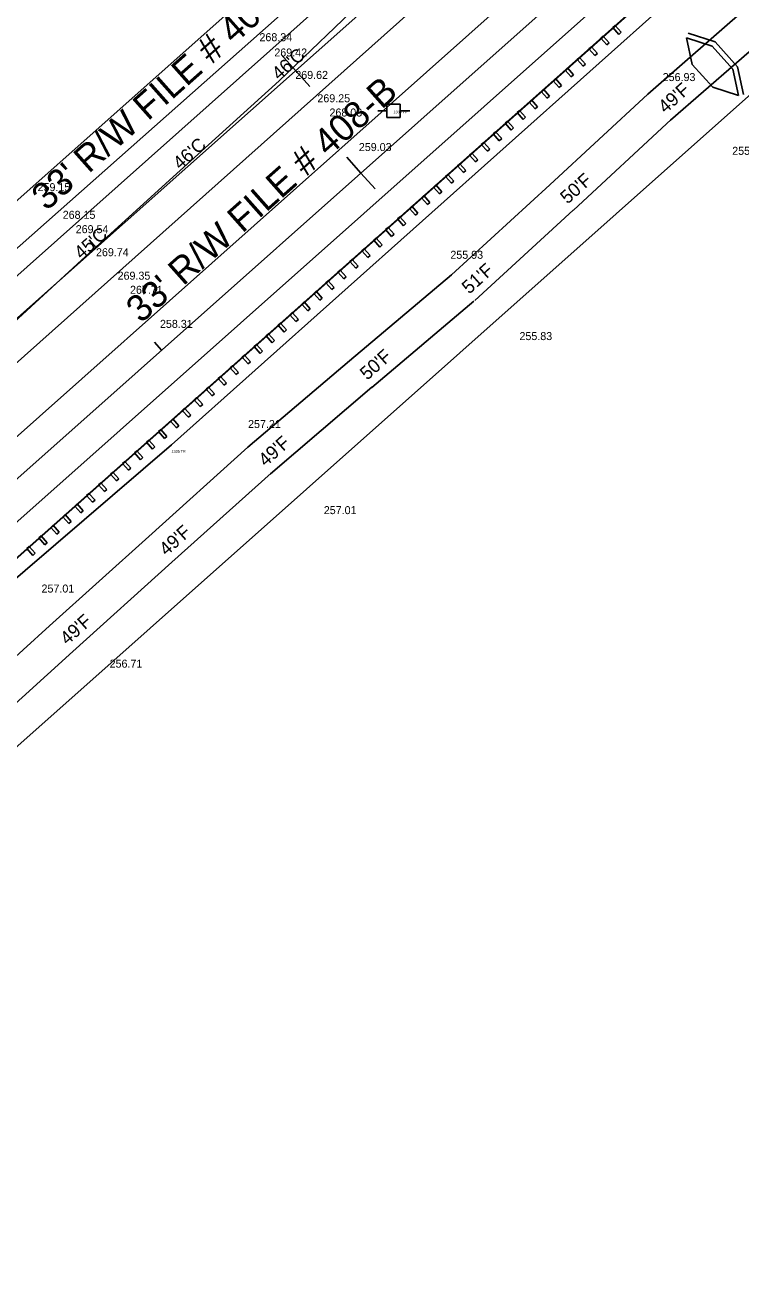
# Model space of a CAD drawing. Extents: x 49683 to 58852, y 49525 to 54803.
# Drawn here: x 53191 to 53459.4, y 50894.8 to 51364.8 of the extents above; entities that cross this region are included whole.
import ezdxf

# ---------------------------------------------------------------- set-up
doc = ezdxf.new("R2010")
doc.units = 0
for name, color, linetype in [('Level 1', 7, 'Continuous'), ('Level 11', 7, 'Continuous'), ('Level 13', 7, 'Continuous'), ('Level 18', 7, 'Continuous'), ('Level 19', 7, 'Continuous'), ('Level 20', 7, 'Continuous'), ('Level 25', 7, 'Continuous'), ('Level 27', 7, 'Continuous'), ('Level 3', 7, 'Continuous'), ('Level 32', 7, 'Continuous'), ('Level 33', 7, 'Continuous'), ('Level 34', 7, 'Continuous'), ('Level 48', 7, 'Continuous'), ('Level 59', 7, 'Continuous'), ('Level 61', 7, 'Continuous'), ('Level 9', 7, 'Continuous')]:
    doc.layers.add(name, color=color, linetype=linetype)

# ---------------------------------------------------------------- blocks, each defined once
blk = doc.blocks.new('PP')
at = {"layer": 'Level 9'}
for p, q in [((2.53, 2.45), (-2.47, 2.45)), ((-2.47, 2.45), (-2.47, -2.55)), ((2.53, -2.55), (2.53, 2.45)), ((-5.91, -0.11), (-2.44, -0.11)), ((-2.47, -2.55), (2.53, -2.55)), ((2.45, -0.11), (6.09, -0.11))]:
    blk.add_line(p, q, dxfattribs=at)

msp = doc.modelspace()

# ---------------------------------------------------------------- linework, layer by layer
at = {"layer": 'Level 1'}
for p, q in [((52544.81, 50683.3), (55534.58, 53340.86)), ((53292.35, 51347.78), (53287.03, 51353.76)), ((53297.66, 51341.8), (53292.35, 51347.78)), ((53217.61, 51281.34), (53214.95, 51284.33))]:
    msp.add_line(p, q, dxfattribs=at)
at = {"layer": 'Level 11'}
for p, q in [((53245.86, 51207.55), (53944.24, 51830.77)), ((53157.7, 51254.45), (53424.49, 51490.93)), ((52882.73, 50895.61), (53245.86, 51207.55))]:
    msp.add_line(p, q, dxfattribs=at)
at = {"layer": 'Level 13'}
for p, q in [((52637.37, 50809.73), (53363.85, 51455.49)), ((53407.7, 51406.16), (52566.74, 50658.64))]:
    msp.add_line(p, q, dxfattribs=at)
at = {"layer": 'Level 18'}
for p, q in [((53286.2, 51343.93), (53322.27, 51378.61)), ((53424.42, 51338.95), (53462.1, 51371.82)), ((53432.96, 51329.16), (53470.65, 51362.02)), ((53249.14, 51310.36), (53286.2, 51343.93)), ((53387.69, 51305.01), (53424.42, 51338.95)), ((53396.52, 51295.46), (53433.24, 51329.41)), ((53212.1, 51276.77), (53249.14, 51310.36)), ((53350.81, 51271.24), (53387.69, 51305.01)), ((53359.59, 51261.65), (53396.47, 51295.42)), ((53175.25, 51242.97), (53212.1, 51276.77)), ((53312.59, 51238.98), (53350.81, 51271.24)), ((53320.98, 51229.04), (53359.2, 51261.31)), ((53274.51, 51206.56), (53312.59, 51238.98)), ((53282.94, 51196.66), (53321.02, 51229.08)), ((53237.33, 51173.13), (53274.51, 51206.56)), ((53246.02, 51163.46), (53283.2, 51196.89)), ((53200.16, 51139.69), (53237.33, 51173.13)), ((53208.85, 51130.02), (53246.02, 51163.46)), ((53163.11, 51106.1), (53200.16, 51139.69)), ((53171.84, 51096.47), (53208.89, 51130.05))]:
    msp.add_line(p, q, dxfattribs=at)
at = {"layer": 'Level 19'}
for p, q in [((52714.15, 50773.62), (54181.77, 52078.16)), ((53316.9, 51309.39), (53311.58, 51315.37)), ((53316.9, 51309.39), (53322.21, 51303.41)), ((53242.16, 51242.96), (53239.5, 51245.95))]:
    msp.add_line(p, q, dxfattribs=at)
at = {"layer": 'Level 20'}
for p, q in [((52706.17, 50782.58), (53452.43, 51445.92)), ((52722.12, 50764.65), (53468.37, 51427.98))]:
    msp.add_line(p, q, dxfattribs=at)
at = {"layer": 'Level 27'}
for p, q in [((52957.81, 50960.77), (53475.02, 51420.51)), ((52957.97, 50960.58), (53475.18, 51420.32)), ((53411.35, 51363.91), (53412.23, 51364.7)), ((53413.61, 51361.37), (53411.35, 51363.91)), ((53412.23, 51364.7), (53414.49, 51362.16)), ((53406.87, 51359.93), (53407.75, 51360.71)), ((53409.13, 51357.39), (53406.87, 51359.93)), ((53407.75, 51360.71), (53410.01, 51358.17)), ((53414.49, 51362.16), (53413.61, 51361.37)), ((53402.38, 51355.94), (53403.27, 51356.73)), ((53404.64, 51353.4), (53402.38, 51355.94)), ((53403.27, 51356.73), (53405.52, 51354.19)), ((53405.52, 51354.19), (53404.64, 51353.4)), ((53410.01, 51358.17), (53409.13, 51357.39)), ((53397.9, 51351.96), (53398.78, 51352.74)), ((53400.16, 51349.41), (53397.9, 51351.96)), ((53398.78, 51352.74), (53401.04, 51350.2)), ((53401.04, 51350.2), (53400.16, 51349.41)), ((53388.93, 51343.98), (53389.81, 51344.77)), ((53389.81, 51344.77), (53392.07, 51342.23)), ((53393.41, 51347.97), (53394.3, 51348.76)), ((53395.67, 51345.43), (53393.41, 51347.97)), ((53394.3, 51348.76), (53396.56, 51346.21)), ((53396.56, 51346.21), (53395.67, 51345.43)), ((53384.44, 51340), (53385.33, 51340.78)), ((53385.33, 51340.78), (53387.59, 51338.24)), ((53391.19, 51341.44), (53388.93, 51343.98)), ((53392.07, 51342.23), (53391.19, 51341.44)), ((53379.96, 51336.01), (53380.84, 51336.8)), ((53382.22, 51333.47), (53379.96, 51336.01)), ((53380.84, 51336.8), (53383.1, 51334.26)), ((53386.7, 51337.46), (53384.44, 51340)), ((53387.59, 51338.24), (53386.7, 51337.46)), ((53375.48, 51332.03), (53376.36, 51332.81)), ((53377.73, 51329.48), (53375.48, 51332.03)), ((53376.36, 51332.81), (53378.62, 51330.27)), ((53383.1, 51334.26), (53382.22, 51333.47)), ((53370.99, 51328.04), (53371.87, 51328.82)), ((53373.25, 51325.5), (53370.99, 51328.04)), ((53371.87, 51328.82), (53374.13, 51326.28)), ((53374.13, 51326.28), (53373.25, 51325.5)), ((53378.62, 51330.27), (53377.73, 51329.48)), ((53366.51, 51324.05), (53367.39, 51324.84)), ((53368.76, 51321.51), (53366.51, 51324.05)), ((53367.39, 51324.84), (53369.65, 51322.3)), ((53369.65, 51322.3), (53368.76, 51321.51)), ((53357.54, 51316.08), (53358.42, 51316.87)), ((53358.42, 51316.87), (53360.68, 51314.32)), ((53362.02, 51320.07), (53362.91, 51320.85)), ((53364.28, 51317.53), (53362.02, 51320.07)), ((53362.91, 51320.85), (53365.16, 51318.31)), ((53365.16, 51318.31), (53364.28, 51317.53)), ((53353.05, 51312.09), (53353.94, 51312.88)), ((53355.31, 51309.55), (53353.05, 51312.09)), ((53353.94, 51312.88), (53356.2, 51310.34)), ((53359.8, 51313.54), (53357.54, 51316.08)), ((53360.68, 51314.32), (53359.8, 51313.54)), ((53348.57, 51308.11), (53349.45, 51308.89)), ((53350.83, 51305.57), (53348.57, 51308.11)), ((53349.45, 51308.89), (53351.71, 51306.35)), ((53356.2, 51310.34), (53355.31, 51309.55)), ((53344.08, 51304.12), (53344.97, 51304.91)), ((53346.34, 51301.58), (53344.08, 51304.12)), ((53344.97, 51304.91), (53347.23, 51302.37)), ((53351.71, 51306.35), (53350.83, 51305.57)), ((53339.6, 51300.14), (53340.48, 51300.92)), ((53341.86, 51297.59), (53339.6, 51300.14)), ((53340.48, 51300.92), (53342.74, 51298.38)), ((53342.74, 51298.38), (53341.86, 51297.59)), ((53347.23, 51302.37), (53346.34, 51301.58)), ((53335.12, 51296.15), (53336, 51296.93)), ((53337.37, 51293.61), (53335.12, 51296.15)), ((53336, 51296.93), (53338.26, 51294.39)), ((53338.26, 51294.39), (53337.37, 51293.61)), ((53326.15, 51288.18), (53327.03, 51288.96)), ((53327.03, 51288.96), (53329.29, 51286.42)), ((53330.63, 51292.16), (53331.51, 51292.95)), ((53332.89, 51289.62), (53330.63, 51292.16)), ((53331.51, 51292.95), (53333.77, 51290.41)), ((53333.77, 51290.41), (53332.89, 51289.62)), ((53321.66, 51284.19), (53322.55, 51284.98)), ((53323.92, 51281.65), (53321.66, 51284.19)), ((53322.55, 51284.98), (53324.8, 51282.43)), ((53328.4, 51285.64), (53326.15, 51288.18)), ((53329.29, 51286.42), (53328.4, 51285.64)), ((53317.18, 51280.21), (53318.06, 51280.99)), ((53319.44, 51277.66), (53317.18, 51280.21)), ((53318.06, 51280.99), (53320.32, 51278.45)), ((53324.8, 51282.43), (53323.92, 51281.65)), ((53312.69, 51276.22), (53313.58, 51277)), ((53314.95, 51273.68), (53312.69, 51276.22)), ((53313.58, 51277), (53315.83, 51274.46)), ((53315.83, 51274.46), (53314.95, 51273.68)), ((53320.32, 51278.45), (53319.44, 51277.66)), ((53308.21, 51272.23), (53309.09, 51273.02)), ((53310.47, 51269.69), (53308.21, 51272.23)), ((53309.09, 51273.02), (53311.35, 51270.48)), ((53311.35, 51270.48), (53310.47, 51269.69)), ((53299.24, 51264.26), (53300.12, 51265.05)), ((53300.12, 51265.05), (53302.38, 51262.5)), ((53303.72, 51268.25), (53304.61, 51269.03)), ((53305.98, 51265.71), (53303.72, 51268.25)), ((53304.61, 51269.03), (53306.87, 51266.49)), ((53306.87, 51266.49), (53305.98, 51265.71)), ((53294.76, 51260.27), (53295.64, 51261.06)), ((53297.01, 51257.73), (53294.76, 51260.27)), ((53295.64, 51261.06), (53297.9, 51258.52)), ((53301.5, 51261.72), (53299.24, 51264.26)), ((53302.38, 51262.5), (53301.5, 51261.72)), ((53290.27, 51256.29), (53291.15, 51257.07)), ((53292.53, 51253.75), (53290.27, 51256.29)), ((53291.15, 51257.07), (53293.41, 51254.53)), ((53297.9, 51258.52), (53297.01, 51257.73)), ((53285.79, 51252.3), (53286.67, 51253.09)), ((53288.04, 51249.76), (53285.79, 51252.3)), ((53286.67, 51253.09), (53288.93, 51250.55)), ((53293.41, 51254.53), (53292.53, 51253.75)), ((53281.3, 51248.32), (53282.19, 51249.1)), ((53283.56, 51245.77), (53281.3, 51248.32)), ((53282.19, 51249.1), (53284.44, 51246.56)), ((53284.44, 51246.56), (53283.56, 51245.77)), ((53288.93, 51250.55), (53288.04, 51249.76)), ((53276.82, 51244.33), (53277.7, 51245.11)), ((53279.08, 51241.79), (53276.82, 51244.33)), ((53277.7, 51245.11), (53279.96, 51242.57)), ((53279.96, 51242.57), (53279.08, 51241.79)), ((53267.85, 51236.36), (53268.73, 51237.14)), ((53268.73, 51237.14), (53270.99, 51234.6)), ((53272.33, 51240.34), (53273.22, 51241.13)), ((53274.59, 51237.8), (53272.33, 51240.34)), ((53273.22, 51241.13), (53275.47, 51238.59)), ((53275.47, 51238.59), (53274.59, 51237.8)), ((53263.36, 51232.37), (53264.25, 51233.16)), ((53265.62, 51229.83), (53263.36, 51232.37)), ((53264.25, 51233.16), (53266.51, 51230.61)), ((53270.11, 51233.82), (53267.85, 51236.36)), ((53270.99, 51234.6), (53270.11, 51233.82)), ((53258.88, 51228.38), (53259.76, 51229.17)), ((53261.14, 51225.84), (53258.88, 51228.38)), ((53259.76, 51229.17), (53262.02, 51226.63)), ((53266.51, 51230.61), (53265.62, 51229.83)), ((53254.39, 51224.4), (53255.28, 51225.18)), ((53256.65, 51221.86), (53254.39, 51224.4)), ((53255.28, 51225.18), (53257.54, 51222.64)), ((53257.54, 51222.64), (53256.65, 51221.86)), ((53262.02, 51226.63), (53261.14, 51225.84)), ((53249.91, 51220.41), (53250.79, 51221.2)), ((53252.17, 51217.87), (53249.91, 51220.41)), ((53250.79, 51221.2), (53253.05, 51218.66)), ((53253.05, 51218.66), (53252.17, 51217.87)), ((53240.94, 51212.44), (53241.82, 51213.23)), ((53241.82, 51213.23), (53244.08, 51210.68)), ((53245.43, 51216.43), (53246.31, 51217.21)), ((53247.68, 51213.88), (53245.43, 51216.43)), ((53246.31, 51217.21), (53248.57, 51214.67)), ((53248.57, 51214.67), (53247.68, 51213.88)), ((53236.46, 51208.45), (53237.34, 51209.24)), ((53237.34, 51209.24), (53239.6, 51206.7)), ((53243.2, 51209.9), (53240.94, 51212.44)), ((53244.08, 51210.68), (53243.2, 51209.9)), ((53231.97, 51204.47), (53232.86, 51205.25)), ((53234.23, 51201.93), (53231.97, 51204.47)), ((53232.86, 51205.25), (53235.11, 51202.71)), ((53238.72, 51205.91), (53236.46, 51208.45)), ((53239.6, 51206.7), (53238.72, 51205.91)), ((53227.49, 51200.48), (53228.37, 51201.27)), ((53229.75, 51197.94), (53227.49, 51200.48)), ((53228.37, 51201.27), (53230.63, 51198.73)), ((53235.11, 51202.71), (53234.23, 51201.93)), ((53223, 51196.5), (53223.89, 51197.28)), ((53225.26, 51193.95), (53223, 51196.5)), ((53223.89, 51197.28), (53226.15, 51194.74)), ((53226.15, 51194.74), (53225.26, 51193.95)), ((53230.63, 51198.73), (53229.75, 51197.94)), ((53218.52, 51192.51), (53219.4, 51193.29)), ((53220.78, 51189.97), (53218.52, 51192.51)), ((53219.4, 51193.29), (53221.66, 51190.75)), ((53221.66, 51190.75), (53220.78, 51189.97)), ((53209.55, 51184.54), (53210.43, 51185.32)), ((53210.43, 51185.32), (53212.69, 51182.78)), ((53214.03, 51188.52), (53214.92, 51189.31)), ((53216.29, 51185.98), (53214.03, 51188.52)), ((53214.92, 51189.31), (53217.18, 51186.77)), ((53217.18, 51186.77), (53216.29, 51185.98)), ((53205.07, 51180.55), (53205.95, 51181.34)), ((53207.32, 51178.01), (53205.07, 51180.55)), ((53205.95, 51181.34), (53208.21, 51178.79)), ((53211.81, 51182), (53209.55, 51184.54)), ((53212.69, 51182.78), (53211.81, 51182)), ((53200.58, 51176.56), (53201.46, 51177.35)), ((53202.84, 51174.02), (53200.58, 51176.56)), ((53201.46, 51177.35), (53203.72, 51174.81)), ((53208.21, 51178.79), (53207.32, 51178.01)), ((53196.1, 51172.58), (53196.98, 51173.36)), ((53198.36, 51170.04), (53196.1, 51172.58)), ((53196.98, 51173.36), (53199.24, 51170.82)), ((53203.72, 51174.81), (53202.84, 51174.02)), ((53191.61, 51168.59), (53192.5, 51169.38)), ((53193.87, 51166.05), (53191.61, 51168.59)), ((53192.5, 51169.38), (53194.75, 51166.84)), ((53194.75, 51166.84), (53193.87, 51166.05)), ((53199.24, 51170.82), (53198.36, 51170.04))]:
    msp.add_line(p, q, dxfattribs=at)
at = {"layer": 'Level 3'}
for p, q in [((53162.5, 51248.32), (53434.09, 51489.84)), ((53179.35, 51230.72), (53449.72, 51471.81))]:
    msp.add_line(p, q, dxfattribs=at)
at = {"layer": 'Level 33'}
msp.add_line((52768.8, 50721.85), (53711.35, 51559.67), dxfattribs=at)
at = {"layer": 'Level 34'}
for p, q in [((53441.09, 51350.12), (53438.99, 51360.03)), ((53438.99, 51360.03), (53448.63, 51356.9)), ((53449.68, 51358.53), (53439.57, 51361.82)), ((53448.63, 51356.9), (53456.37, 51348.31)), ((53458.1, 51349.19), (53449.68, 51358.53)), ((53448.83, 51341.52), (53441.09, 51350.12)), ((53456.37, 51348.31), (53458.48, 51338.39)), ((53460.31, 51338.78), (53458.1, 51349.19)), ((53458.48, 51338.39), (53448.83, 51341.52))]:
    msp.add_line(p, q, dxfattribs=at)

# ---------------------------------------------------------------- block references
at = {"layer": 'Level 9'}
msp.add_blockref('PP', (53329.09, 51332.81), dxfattribs=at)

# ---------------------------------------------------------------- texts
at = {"layer": 'Level 25'}
for p in [(53199, 51294.91), (53234.4, 51252.78)]:
    msp.add_text("33' R/W FILE # 408-B", height=10, rotation=41.6333, dxfattribs=at).set_placement(p)
at = {"layer": 'Level 32'}
for s, p in [('268.34', (53278.83, 51358.8)), ('269.42', (53284.41, 51353.07)), ('269.62', (53292.27, 51344.67)), ('256.93', (53430.02, 51343.85)), ('269.25', (53300.55, 51335.91)), ('268.03', (53305.09, 51330.58)), ('259.03', (53316.1, 51317.62)), ('255.83', (53456.09, 51316.21)), ('259.15', (53195.65, 51302.59)), ('268.15', (53205.06, 51292.22)), ('269.54', (53209.93, 51286.84)), ('269.74', (53217.54, 51278.2)), ('255.93', (53350.42, 51277.24)), ('269.35', (53225.64, 51269.4)), ('267.71', (53230.3, 51264.11)), ('258.31', (53241.53, 51251.34)), ('255.83', (53376.32, 51246.76)), ('257.21', (53274.56, 51213.8)), ('257.01', (53302.96, 51181.52)), ('257.01', (53197.12, 51152.12)), ('256.71', (53222.65, 51123.97))]:
    msp.add_text(s, height=3, dxfattribs=at).set_placement(p)
at = {"layer": 'Level 48'}
for s, rotation, p in [("46'C", 41.6334, (53286.2, 51343.93)), ("49'F", 41.6334, (53431.06, 51331.48)), ("46'C", 41.6334, (53249.14, 51310.36)), ("50'F", 41.6333, (53394.34, 51297.53)), ("45'C", 41.6334, (53212.1, 51276.77)), ("51'F", 41.6334, (53357.45, 51263.77)), ("50'F", 41.6334, (53319.24, 51231.5)), ("49'F", 41.6334, (53281.16, 51199.08)), ("49'F", 41.6334, (53243.97, 51165.65)), ("49'F", 41.6334, (53206.8, 51132.21))]:
    msp.add_text(s, height=5, rotation=rotation, dxfattribs=at).set_placement(p)
at = {"layer": 'Level 59'}
msp.add_text('1336 PP', height=1, dxfattribs=at).set_placement((53329.09, 51331.81))
at = {"layer": 'Level 61'}
msp.add_text('1335 TR', height=1, dxfattribs=at).set_placement((53245.86, 51204.55))

doc.saveas('drawing.dxf')
